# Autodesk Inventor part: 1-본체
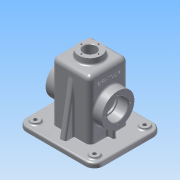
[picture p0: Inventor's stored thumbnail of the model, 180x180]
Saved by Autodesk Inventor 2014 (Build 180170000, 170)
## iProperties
Created: 2015-12
Part Number: 1-본체
Material: 알루미늄 6061
Document SubType Name: Modeling
Designer: Administrator
Density: 2.71 g/cm^3
Appearance: 알루미늄 - 평지
Mass: 803.266 g
Surface Area: 909.178 cm^2
Volume: 296.408 cm^3
Author: Administrator
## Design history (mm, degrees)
sketch "스케치1"
  geometry: L1 (50, -57.5)-(-50, -57.5); L2 (-65, -42.5)-(-65, 42.5); L3 (-50, 57.5)-(50, 57.5); L4 (65, 42.5)-(65, -42.5); L5 (65, -57.5)-(-65, 57.5); L6 (-65, -57.5)-(65, 57.5); A1 r 15 centre (-50, 42.5) between (-50, 57.5) and (-65, 42.5); A2 r 15 centre (-50, -42.5) between (-65, -42.5) and (-50, -57.5); A3 r 15 centre (50, -42.5) between (50, -57.5) and (65, -42.5); A4 r 15 centre (50, 42.5) between (65, 42.5) and (50, 57.5); 1 further point
  constraints: 12 end point, 8 point on circle, 8 point on line, 8 tangent, 4 centre point, 3 equal radius, 2 midpoint, 2 parallel, 1 horizontal, 1 perpendicular
  dimensions: "d0" = 115 distance of L6.start L5.end; "d1" = 130 distance of L5.end L6.end; "d2" = 15 radius of A1
extrude "돌출1" new body sketch "스케치1" distance "d3" = 10; taper "d4" = 0 deg
sketch "스케치2"
  geometry: L1 (24.5, -32.5)-(-24.5, -32.5); L2 (-32.5, -24.5)-(-32.5, 24.5); L3 (-24.5, 32.5)-(24.5, 32.5); L4 (32.5, 24.5)-(32.5, -24.5); L5 (32.5, -32.5)-(-32.5, 32.5); L6 (-32.5, -32.5)-(32.5, 32.5); A1 r 8 centre (-24.5, 24.5) between (-24.5, 32.5) and (-32.5, 24.5); A2 r 8 centre (24.5, 24.5) between (32.5, 24.5) and (24.5, 32.5); A3 r 8 centre (24.5, -24.5) between (24.5, -32.5) and (32.5, -24.5); A4 r 8 centre (-24.5, -24.5) between (-32.5, -24.5) and (-24.5, -32.5); 1 further point
  constraints: 12 end point, 8 point on circle, 8 point on line, 8 tangent, 4 centre point, 3 equal radius, 2 midpoint, 2 parallel, 1 horizontal, 1 perpendicular
  dimensions: "d5" = 65 distance of L5.end L6.end; "d6" = 65 distance of L6.start L5.end; "d7" = 8 radius of A1
extrude "돌출2" join sketch "스케치2" distance "d8" = 100; taper "d9" = 0 deg
sketch "스케치3"
  geometry: L1 (50, 57.5)-(-50, 57.5) reference; L2 (-65, 42.5)-(-65, -42.5) reference; L3 (-50, -57.5)-(50, -57.5) reference; L4 (65, -42.5)-(65, 42.5) reference; L5 (-50, 52.5)-(50, 52.5); L6 (60, 42.5)-(60, -42.5); L7 (50, -52.5)-(-50, -52.5); L8 (-60, -42.5)-(-60, 42.5); A1 r 15 centre (-50, 42.5) between (-50, 57.5) and (-65, 42.5) reference; A2 r 15 centre (-50, -42.5) between (-65, -42.5) and (-50, -57.5) reference; A3 r 15 centre (50, -42.5) between (50, -57.5) and (65, -42.5) reference; A4 r 15 centre (50, 42.5) between (65, 42.5) and (50, 57.5) reference; A5 r 10 centre (50, 42.5) between (60, 42.5) and (50, 52.5); A6 r 10 centre (50, -42.5) between (50, -52.5) and (60, -42.5); A7 r 10 centre (-50, -42.5) between (-60, -42.5) and (-50, -52.5); A8 r 10 centre (-50, 42.5) between (-50, 52.5) and (-60, 42.5); 1 further point
  constraints: 8 end point, 8 point on circle, 4 centre point, 7 other
  dimensions: "d10" = 5 distance between parallel lines of L2 L8
extrude "돌출3" cut sketch "스케치3" distance "d11" = 2; taper "d12" = 0 deg
node "작업 평면1"
sketch "스케치4"
  geometry: L1 (0, 85)-(0, 0) reference; L2 (0, 0)-(0, -15) reference; L3 (0, 100)-(0, 85) reference; L4 (0, 10)-(-100, 10) reference; L5 (0, -5)-(-85.069, 10); L6 (8, -15)-(0, -15) reference; L7 (0, 75)-(-100, 75) reference; L8 (-85.069, 10)-(-85.069, 75); L9 (-85.069, 75)-(0, 90); L10 (8, 100)-(0, 100) reference; 1 further point
  constraints: 6 end point, 4 point on line, 1 perpendicular
  dimensions: "d15" = 10 distance of L3.start L9.end; "d16" = 10 deg angle of L9 L10; "d17" = 10 deg angle of L5 L6
extrude "돌출4" join sketch "스케치4" stored distance "d18" = 10; taper "d19" = 0 deg
sketch "스케치5"
  geometry: L1 (24.5, -27.5)-(-24.5, -27.5); L2 (-27.5, -24.5)-(-27.5, 24.5); L3 (-24.5, 27.5)-(24.5, 27.5); L4 (27.5, 24.5)-(27.5, -24.5); L5 (27.5, -27.5)-(-27.5, 27.5); L6 (-27.5, -27.5)-(27.5, 27.5); A1 r 3 centre (-24.5, 24.5) between (-24.5, 27.5) and (-27.5, 24.5); A2 r 3 centre (24.5, 24.5) between (27.5, 24.5) and (24.5, 27.5); A3 r 3 centre (24.5, -24.5) between (24.5, -27.5) and (27.5, -24.5); A4 r 3 centre (-24.5, -24.5) between (-27.5, -24.5) and (-24.5, -27.5); 1 further point
  constraints: 12 end point, 8 point on circle, 8 point on line, 8 tangent, 4 centre point, 3 equal radius, 2 midpoint, 2 parallel, 1 horizontal, 1 perpendicular
  dimensions: "d20" = 55 distance of L5.end L6.end; "d21" = 55 distance of L6.start L5.end; "d22" = 3 radius of A1
extrude "돌출5" cut sketch "스케치5" distance "d23" = 105; taper "d24" = 0 deg
sketch "스케치6"
  geometry: C1 r 20 at (0, 0); 1 further point
  constraints: 1 centre point, 1 coincident
  dimensions: "d25" = 40 diameter of C1
extrude "돌출6" join sketch "스케치6" distance "d26" = 10; taper "d27" = -5 deg
node "작업 평면2"
sketch "스케치7"
  geometry: L1 (10, 67)-(10, -18) reference; L2 (8, -18)-(8, 67) reference; C1 r 27.5 at (-45, 24.5); 2 further points
  constraints: 1 centre point, 1 horizontal alignment, 1 midpoint
  dimensions: "d29" = 55 diameter of C1; "d31" = 55 distance from line of L1 C1.centre
extrude "돌출7" join sketch "스케치7" stored distance "d32" = 10; taper "d33" = 0 deg
hole "구멍1" diameter "d36" = 30; stored, may be unused: countersink angle "d40" = 90 deg, drill point angle "d42" = 118 deg; dims "d37" = 6, "d38" = 35, "d39" = 17, "d41" = 8, "d43" = 10, "d44" = 10
sketch "스케치8"
  geometry: C1 r 17.5 at (0, 0) reference; C2 r 27.5 at (0, 0) reference; A1 r 21 centre (0, 0) between (0, -21) and (-21, 0); 3 further points
  constraints: 4 point on circle, 2 horizontal alignment, 2 vertical alignment, 1 centre point, 1 coincident
  dimensions: "d45" = 42 diameter of A1
hole "구멍2" sketch "스케치8" at (0, -21), (-21, 0), (0, 21), (21, 0) diameter "d46" = 3.242; stored, may be unused: countersink angle "d50" = 90 deg, drill point angle "d52" = 118 deg; dims "d47" = 8, "d48" = 42, "d49" = 17, "d51" = 10
hole "구멍3" diameter "d55" = 21; stored, may be unused: countersink angle "d59" = 90 deg, drill point angle "d61" = 118 deg; dims "d53" = 10, "d54" = 10, "d56" = 8, "d57" = 42, "d58" = 17, "d60" = 10
sketch "스케치9"
  geometry: C1 r 10.5 at (0, 0) reference; C2 r 19.125 at (0, 0) reference; A1 r 14.5 centre (0, 0) between (14.5, 0) and (0, 14.5); 2 further points
  constraints: 4 point on circle, 2 horizontal alignment, 2 vertical alignment, 1 centre point, 1 coincident
  dimensions: "d62" = 29 diameter of A1
hole "구멍4" sketch "스케치9" at (14.5, 0), (0, 14.5), (-14.5, 0), (0, -14.5) diameter "d63" = 2.459; stored, may be unused: countersink angle "d67" = 90 deg, drill point angle "d69" = 118 deg; dims "d64" = 7, "d65" = 4, "d66" = 2, "d68" = 9
sketch "스케치10"
  geometry: C1 r 7.5 at (-50, 42.5); C2 r 7.5 at (50, 42.5); C3 r 7.5 at (-50, -42.5); C4 r 7.5 at (50, -42.5); A1 r 15 centre (-50, 42.5) between (-50, 57.5) and (-65, 42.5) reference; A2 r 15 centre (-50, -42.5) between (-65, -42.5) and (-50, -57.5) reference; A3 r 15 centre (50, -42.5) between (50, -57.5) and (65, -42.5) reference; A4 r 15 centre (50, 42.5) between (65, 42.5) and (50, 57.5) reference; 1 further point
  constraints: 4 centre point, 4 coincident, 1 equal radius
  dimensions: "d70" = 15 diameter of C1; "d71" = 15 diameter of C2; "d72" = 15 diameter of C3
extrude "돌출8" join sketch "스케치10" distance "d73" = 3; taper "d74" = 0 deg
fillet "모깎기1" dims "d82" = 8
fillet "모깎기5" dims "d91" = 3
node "작업 평면4"
sketch "스케치13"
  geometry: L1 (17.5, 0)-(17.5, 32.51) reference; L2 (17.5, 17.5)-(2.5, 17.5) reference; L3 (100, 0)-(0, 0) reference; L4 (7.5, 19)-(7.5, 0); L5 (22.5, -10)-(22.5, 95) reference; L6 (7.5, 19)-(19.04, 19); L7 (19.04, 19)-(19.04, 0); 1 further point
  constraints: 6 end point, 3 perpendicular, 2 point on line
  dimensions: "d92" = 15 distance between parallel lines of L4 L5; "d93" = 11.54026 distance of L4.start L6.end; "d94" = 19 distance of L6.end L7.end
extrude "돌출10" join sketch "스케치13" stored distance "d95" = 6; taper "d96" = 0 deg
fillet "모깎기6" dims "d97" = 3
fillet "모깎기7" dims "d98" = 1
fillet "모깎기8" dims "d99" = 3
fillet "모깎기10" dims "d101" = 3
chamfer "모따기1" distance "d102" = 1; stored, may be unused: second distance "d103" = 2, angle "d104" = 45 deg
sketch "스케치14"
  geometry: L1 (-65, -19.125)-(-65, 19.125) reference; 3 further points
  constraints: 1 horizontal alignment, 1 midpoint, 1 other
  dimensions: "d105" = 26 distance of point (-39, 0) point (-65, 0)
feature "엠보싱1" sketch "스케치14" dims "d5" = 65, "d6" = 65, "d7" = 8, "d106" = 0.5, "d107" = 0
fillet "모깎기11" dims "d108" = 3
fillet "모깎기12" dims "d109" = 3
hole "구멍6" diameter "d112" = 6; stored, may be unused: countersink angle "d116" = 90 deg, drill point angle "d118" = 118 deg; dims "d110" = 10, "d111" = 10, "d113" = 6, "d114" = 4, "d115" = 2, "d117" = 8
hole "구멍7" diameter "d121" = 6; stored, may be unused: countersink angle "d125" = 90 deg, drill point angle "d127" = 118 deg; dims "d119" = 10, "d120" = 10, "d122" = 6, "d123" = 4, "d124" = 2, "d126" = 8
hole "구멍8" diameter "d130" = 6; stored, may be unused: countersink angle "d134" = 90 deg, drill point angle "d136" = 118 deg; dims "d128" = 10, "d129" = 10, "d131" = 6, "d132" = 4, "d133" = 2, "d135" = 8
hole "구멍9" diameter "d139" = 6; stored, may be unused: countersink angle "d143" = 90 deg, drill point angle "d145" = 118 deg; dims "d137" = 10, "d138" = 10, "d140" = 6, "d141" = 4, "d142" = 2, "d144" = 8
node "솔리드1"
mirror "대칭1"
mirror "대칭3"
other parameters: "d28" = 15
